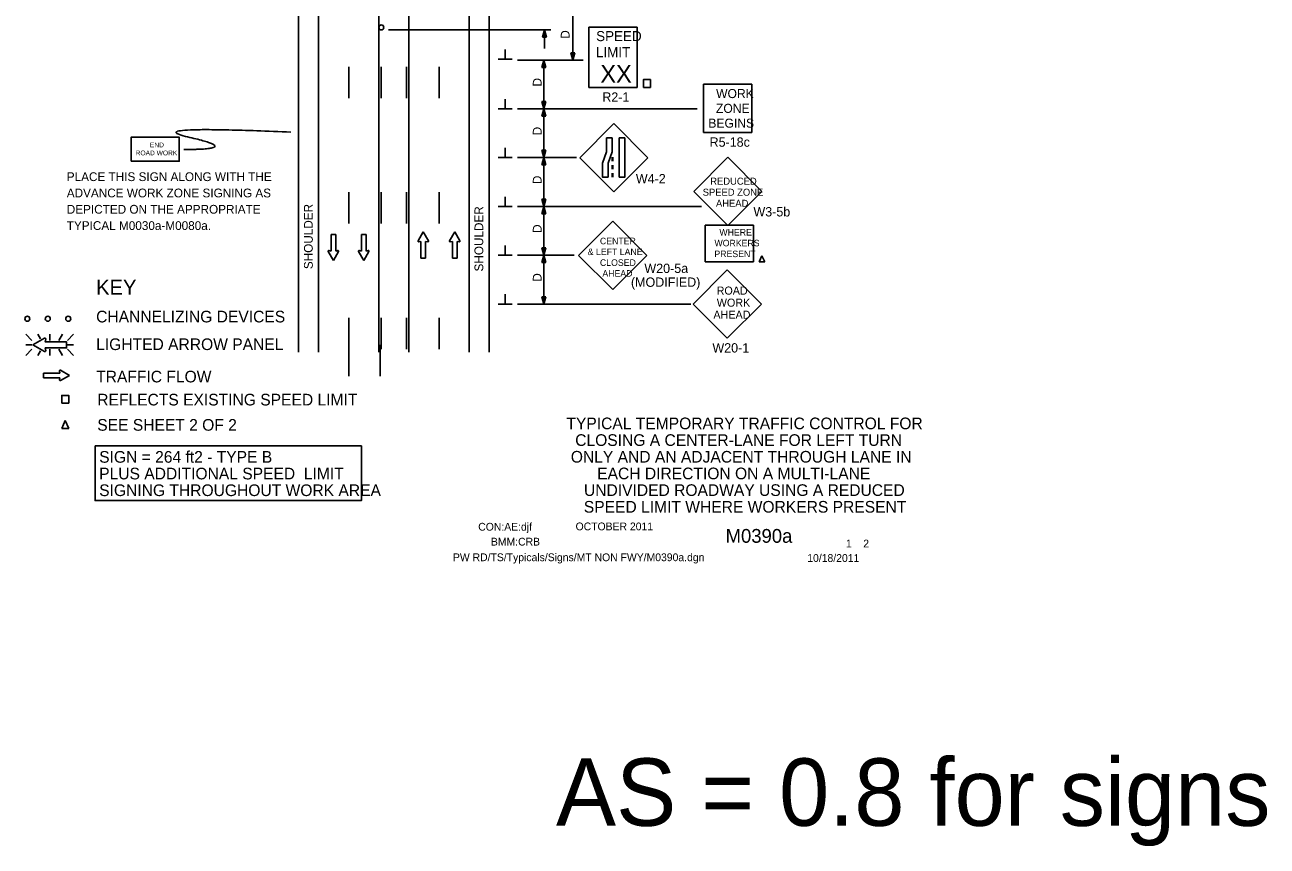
# Model space of a CAD drawing. Extents: x 16729 to 18475, y 5706 to 6927.
# Drawn here: x 16729 to 17719, y 5706 to 6361 of the extents above; entities that cross this region are included whole.
import ezdxf

# ---------------------------------------------------------------- set-up
doc = ezdxf.new("R2010")
doc.units = 0
for name, color, linetype in [('ALI_LEGAL_EX', 7, 'Continuous'), ('BORDER_SIGNAL_WO', 7, 'Continuous'), ('MT_SCRATCH_LEVEL_E', 7, 'Continuous'), ('PAVT_EDGE_EX', 7, 'Continuous'), ('TRAFFIC_SIGNS_PR', 7, 'Continuous'), ('TYPICAL_TEXT_DIMEN_EX', 7, 'Continuous'), ('TYPICAL_TEXT_DIMEN_PR', 7, 'Continuous')]:
    doc.layers.add(name, color=color, linetype=linetype)

msp = doc.modelspace()

# ---------------------------------------------------------------- linework, layer by layer
at = {"layer": 'ALI_LEGAL_EX'}
for points in [[(16987.43, 6327.88), (16987.43, 6302.88)], [(17013.43, 6327.88), (17013.43, 6302.88)], [(17033.43, 6327.88), (17033.43, 6302.88)], [(17059.43, 6327.88), (17059.43, 6302.88)], [(16987.43, 6227.88), (16987.43, 6202.88)], [(17013.43, 6227.88), (17013.43, 6202.88)], [(17033.43, 6227.88), (17033.43, 6202.88)], [(17059.43, 6227.88), (17059.43, 6202.88)], [(16987.43, 6127.88), (16987.43, 6102.88)], [(17013.43, 6127.88), (17013.43, 6102.88)], [(17033.43, 6127.88), (17033.43, 6102.88)], [(17059.43, 6127.88), (17059.43, 6102.88)]]:
    msp.add_lwpolyline(points, dxfattribs=at)
at = {"layer": 'MT_SCRATCH_LEVEL_E'}
for p, q in [((16977.1, 6194.29), (16973.36, 6194.29)), ((16973.36, 6194.29), (16973.36, 6181.03)), ((16977.1, 6194.29), (16973.36, 6194.29)), ((16973.36, 6194.29), (16973.36, 6181.03)), ((16977.1, 6181.03), (16977.1, 6194.29)), ((16977.1, 6181.03), (16977.1, 6194.29)), ((17001.36, 6194.29), (16997.62, 6194.29)), ((16997.62, 6194.29), (16997.62, 6181.03)), ((17001.36, 6194.29), (16997.62, 6194.29)), ((16997.62, 6194.29), (16997.62, 6181.03)), ((17001.36, 6181.03), (17001.36, 6194.29)), ((17001.36, 6181.03), (17001.36, 6194.29)), ((17046.87, 6196.29), (17042.76, 6189.05)), ((17046.87, 6196.29), (17042.76, 6189.05)), ((17043.24, 6188.37), (17045.02, 6188.68)), ((17043.24, 6188.37), (17045.02, 6188.68)), ((17045.02, 6188.68), (17045.02, 6175.42)), ((17045.02, 6188.68), (17045.02, 6175.42)), ((17051.02, 6189.05), (17046.87, 6196.29)), ((17051.02, 6189.05), (17046.87, 6196.29)), ((17048.76, 6175.42), (17048.76, 6188.68)), ((17048.76, 6188.68), (17050.54, 6188.37)), ((17048.76, 6175.42), (17048.76, 6188.68)), ((17048.76, 6188.68), (17050.54, 6188.37)), ((17071.96, 6196.29), (17067.85, 6189.05)), ((17071.96, 6196.29), (17067.85, 6189.05)), ((17068.33, 6188.37), (17070.11, 6188.68)), ((17068.33, 6188.37), (17070.11, 6188.68)), ((17070.11, 6188.68), (17070.11, 6175.42)), ((17070.11, 6188.68), (17070.11, 6175.42)), ((17076.11, 6189.05), (17071.96, 6196.29)), ((17076.11, 6189.05), (17071.96, 6196.29)), ((17073.85, 6175.42), (17073.85, 6188.68)), ((17073.85, 6188.68), (17075.63, 6188.37)), ((17073.85, 6175.42), (17073.85, 6188.68)), ((17073.85, 6188.68), (17075.63, 6188.37)), ((16971.1, 6180.66), (16975.25, 6173.42)), ((16971.1, 6180.66), (16975.25, 6173.42)), ((16973.36, 6181.03), (16971.58, 6181.35)), ((16973.36, 6181.03), (16971.58, 6181.35)), ((16975.25, 6173.42), (16979.36, 6180.66)), ((16975.25, 6173.42), (16979.36, 6180.66)), ((16978.88, 6181.35), (16977.1, 6181.03)), ((16978.88, 6181.35), (16977.1, 6181.03)), ((16995.36, 6180.66), (16999.51, 6173.42)), ((16995.36, 6180.66), (16999.51, 6173.42)), ((16997.62, 6181.03), (16995.84, 6181.35)), ((16997.62, 6181.03), (16995.84, 6181.35)), ((16999.51, 6173.42), (17003.62, 6180.66)), ((16999.51, 6173.42), (17003.62, 6180.66)), ((17003.14, 6181.35), (17001.36, 6181.03)), ((17003.14, 6181.35), (17001.36, 6181.03)), ((17045.02, 6175.42), (17048.76, 6175.42)), ((17045.02, 6175.42), (17048.76, 6175.42)), ((17070.11, 6175.42), (17073.85, 6175.42)), ((17070.11, 6175.42), (17073.85, 6175.42)), ((16757.36, 6083.74), (16744.1, 6083.74)), ((16744.1, 6083.74), (16744.1, 6080)), ((16757.36, 6083.74), (16744.1, 6083.74)), ((16744.1, 6083.74), (16744.1, 6080)), ((16744.1, 6080), (16757.36, 6080)), ((16744.1, 6080), (16757.36, 6080)), ((16757.05, 6085.51), (16757.36, 6083.74)), ((16757.05, 6085.51), (16757.36, 6083.74)), ((16757.36, 6080), (16757.05, 6078.22)), ((16757.36, 6080), (16757.05, 6078.22)), ((16764.97, 6081.89), (16757.73, 6086)), ((16764.97, 6081.89), (16757.73, 6086)), ((16757.73, 6077.74), (16764.97, 6081.89)), ((16757.73, 6077.74), (16764.97, 6081.89))]:
    msp.add_line(p, q, dxfattribs=at)
for centre, start, end in [((17043.17, 6188.83), 150.42484, 279.96381), ((17043.17, 6188.83), 150.42484, 279.96381), ((17050.61, 6188.83), 260.03619, 29.77312), ((17050.61, 6188.83), 260.03619, 29.77312), ((17068.26, 6188.83), 150.42484, 279.96381), ((17068.26, 6188.83), 150.42484, 279.96381), ((17075.7, 6188.83), 260.03619, 29.77312), ((17075.7, 6188.83), 260.03619, 29.77312), ((16971.51, 6180.89), 80.03619, 209.77312), ((16971.51, 6180.89), 80.03619, 209.77312), ((16978.96, 6180.89), 330.42484, 99.96381), ((16978.96, 6180.89), 330.42484, 99.96381), ((16995.77, 6180.89), 80.03619, 209.77312), ((16995.77, 6180.89), 80.03619, 209.77312), ((17003.21, 6180.89), 330.42484, 99.96381), ((17003.21, 6180.89), 330.42484, 99.96381), ((16757.5, 6085.59), 60.42484, 189.96381), ((16757.5, 6085.59), 60.42484, 189.96381), ((16757.51, 6078.15), 170.03619, 299.77312), ((16757.51, 6078.15), 170.03619, 299.77312)]:
    msp.add_arc(centre, 0.463, start, end, dxfattribs=at)
at = {"layer": 'PAVT_EDGE_EX'}
for p, q in [((16947.43, 6859.63), (16947.43, 6100.51)), ((16963.43, 6859.63), (16963.43, 6100.51)), ((17011.43, 6859.63), (17011.43, 6100.51)), ((17035.43, 6859.63), (17035.43, 6100.51)), ((17083.43, 6859.63), (17083.43, 6100.51)), ((17099.43, 6859.63), (17099.43, 6100.51))]:
    msp.add_line(p, q, dxfattribs=at)
for points in [[(16987.43, 6081.34), (16987.43, 6106.34)], [(17012.43, 6081.34), (17012.43, 6106.34)]]:
    msp.add_lwpolyline(points, dxfattribs=at)
at = {"layer": 'TRAFFIC_SIGNS_PR'}
for p, q in [((17178.92, 6359.55), (17217.32, 6359.55)), ((17178.92, 6311.55), (17178.92, 6359.55)), ((17217.32, 6311.55), (17217.32, 6359.55)), ((17178.92, 6311.55), (17217.32, 6311.55)), ((17270.29, 6275.63), (17270.29, 6314.03)), ((17270.29, 6314.03), (17308.69, 6314.03)), ((17308.69, 6275.63), (17308.69, 6314.03)), ((17198.74, 6282.6), (17171.58, 6255.44)), ((17225.89, 6255.44), (17198.74, 6282.6)), ((17270.29, 6275.63), (17308.69, 6275.63)), ((17171.58, 6255.44), (17198.74, 6228.29)), ((17197.49, 6255.93), (17197.49, 6252.73)), ((17197.49, 6249.53), (17197.49, 6246.33)), ((17197.89, 6255.93), (17197.89, 6252.73)), ((17197.89, 6249.53), (17197.89, 6246.33)), ((17198.74, 6228.29), (17225.89, 6255.44)), ((17289.56, 6255.77), (17262.41, 6228.61)), ((17316.71, 6228.61), (17289.56, 6255.77)), ((17197.49, 6243.13), (17197.49, 6239.93)), ((17197.89, 6243.13), (17197.89, 6239.93)), ((17262.41, 6228.61), (17289.56, 6201.46)), ((17289.56, 6201.46), (17316.71, 6228.61)), ((17197.92, 6204.73), (17170.74, 6177.55)), ((17225.11, 6177.55), (17197.92, 6204.73)), ((17271.6, 6201.69), (17310, 6201.69)), ((17271.6, 6172.37), (17271.6, 6201.69)), ((17310, 6172.37), (17310, 6201.69)), ((17170.74, 6177.55), (17197.92, 6150.36)), ((17197.92, 6150.36), (17225.11, 6177.55)), ((17271.6, 6172.37), (17310, 6172.37)), ((17289.18, 6165.92), (17261.99, 6138.73)), ((17316.37, 6138.73), (17289.18, 6165.92)), ((17261.99, 6138.73), (17289.18, 6111.54)), ((17289.18, 6111.54), (17316.37, 6138.73)), ((16730.08, 6114.7), (16735.02, 6109.77)), ((16741.84, 6110.88), (16739.64, 6114.7)), ((16749.16, 6109.77), (16749.16, 6114.7)), ((16756.4, 6109.77), (16759.25, 6114.7)), ((16763.31, 6109.77), (16768.25, 6114.71)), ((16735.02, 6106.21), (16730.08, 6106.21)), ((16730.08, 6097.72), (16735.02, 6102.66)), ((16739.59, 6097.72), (16741.71, 6101.38)), ((16749.16, 6102.66), (16749.16, 6097.72)), ((16759.29, 6097.72), (16756.44, 6102.66)), ((16763.31, 6106.21), (16768.25, 6106.21)), ((16763.31, 6102.66), (16768.25, 6097.72))]:
    msp.add_line(p, q, dxfattribs=at)
for points in [[(17222.33, 6311.55), (17227.93, 6311.55), (17227.93, 6317.72), (17222.33, 6317.72)], [(16814.04, 6252.59), (16852.44, 6252.59), (16852.44, 6271.79), (16814.04, 6271.79)], [(17197.49, 6271.18), (17197.49, 6260), (17194.14, 6251.12), (17194.14, 6239.93), (17189.65, 6239.93), (17189.65, 6251.12), (17192.99, 6260), (17192.99, 6271.18)], [(17207.62, 6271.18), (17207.62, 6239.93), (17203.13, 6239.93), (17203.13, 6271.18)], [(16758.75, 6059.72), (16764.35, 6059.72), (16764.35, 6065.89), (16758.75, 6065.89)]]:
    msp.add_lwpolyline(points, close=True, dxfattribs=at)
for points in [[(17316.75, 6177.31), (17314.52, 6172.37)], [(17314.52, 6172.37), (17316.75, 6177.31)], [(17314.52, 6172.37), (17318.99, 6172.37)], [(17318.99, 6172.37), (17314.52, 6172.37)], [(17318.99, 6172.37), (17316.75, 6177.31)], [(17316.75, 6177.31), (17318.99, 6172.37)], [(16745.09, 6111.49), (16735.8, 6106.21), (16745.09, 6100.89)], [(16745.97, 6101.52), (16745.57, 6103.79), (16762.58, 6103.79), (16762.58, 6108.59), (16745.57, 6108.59), (16745.97, 6110.87)], [(16761.55, 6045.76), (16758.75, 6039.59)], [(16758.75, 6039.59), (16761.55, 6045.76)], [(16764.35, 6039.59), (16761.55, 6045.76)], [(16761.55, 6045.76), (16764.35, 6039.59)], [(16758.75, 6039.59), (16764.35, 6039.59)], [(16764.35, 6039.59), (16758.75, 6039.59)]]:
    msp.add_lwpolyline(points, dxfattribs=at)
for centre in [(17013.45, 6359.33), (17013.45, 6359.33), (16731.34, 6127.04), (16747.64, 6127.04), (16763.94, 6127.04)]:
    msp.add_circle(centre, 2, dxfattribs=at)
for centre, radius, start, end in [((16745.38, 6110.97), 0.598, 350.73078, 118.89165), ((16745.38, 6101.42), 0.597, 241.48329, 9.95933)]:
    msp.add_arc(centre, radius, start, end, dxfattribs=at)
msp.add_open_spline([(16856.03, 6261.97), (16903.27, 6261.97), (16818.24, 6281.32), (16941.34, 6275.83)], degree=2, dxfattribs=at)
at = {"layer": 'TYPICAL_TEXT_DIMEN_EX'}
msp.add_lwpolyline([(16785.26, 6025.6), (16997.53, 6025.6), (16997.53, 5981.98), (16785.26, 5981.98)], close=True, dxfattribs=at)
at = {"layer": 'TYPICAL_TEXT_DIMEN_PR'}
for p, q in [((17166.05, 6372.25), (17166.05, 6333.33)), ((17148.43, 6357.33), (17019.11, 6357.33)), ((17143.43, 6357.33), (17141.86, 6351.47)), ((17143.43, 6357.33), (17143.43, 6342.41)), ((17145, 6351.47), (17143.43, 6357.33)), ((17141.86, 6351.47), (17143.43, 6351.47)), ((17143.43, 6351.47), (17145, 6351.47)), ((17112.19, 6333.98), (17112.19, 6341.77)), ((17166.05, 6333.33), (17164.48, 6339.19)), ((17164.48, 6339.19), (17166.05, 6339.19)), ((17166.05, 6339.19), (17167.62, 6339.19)), ((17167.62, 6339.19), (17166.05, 6333.33)), ((17117.82, 6333.98), (17106.57, 6333.98)), ((17174.43, 6333.33), (17122.07, 6333.33)), ((17141.5, 6327.47), (17143.07, 6333.33)), ((17143.07, 6327.47), (17141.5, 6327.47)), ((17143.07, 6333.33), (17143.07, 6294.41)), ((17143.07, 6333.33), (17144.64, 6327.47)), ((17144.64, 6327.47), (17143.07, 6327.47)), ((17112.19, 6294.41), (17112.19, 6302.19)), ((17143.07, 6294.41), (17141.5, 6300.27)), ((17141.5, 6300.27), (17143.07, 6300.27)), ((17143.07, 6300.27), (17144.64, 6300.27)), ((17144.64, 6300.27), (17143.07, 6294.41)), ((17117.82, 6294.41), (17106.57, 6294.41)), ((17265.06, 6294.41), (17122.07, 6294.41)), ((17141.5, 6288.55), (17143.07, 6294.41)), ((17143.07, 6288.55), (17141.5, 6288.55)), ((17143.07, 6294.41), (17143.07, 6255.49)), ((17143.07, 6294.41), (17144.64, 6288.55)), ((17144.64, 6288.55), (17143.07, 6288.55)), ((17112.19, 6255.49), (17112.19, 6263.28)), ((17143.07, 6255.49), (17141.5, 6261.35)), ((17141.5, 6261.35), (17143.07, 6261.35)), ((17143.07, 6261.35), (17144.64, 6261.35)), ((17144.64, 6261.35), (17143.07, 6255.49)), ((17117.82, 6255.49), (17106.57, 6255.49)), ((17168.96, 6255.49), (17122.07, 6255.49)), ((17141.5, 6249.63), (17143.07, 6255.49)), ((17143.07, 6249.63), (17141.5, 6249.63)), ((17143.07, 6255.49), (17143.07, 6216.57)), ((17143.07, 6255.49), (17144.64, 6249.63)), ((17144.64, 6249.63), (17143.07, 6249.63)), ((17112.19, 6216.57), (17112.19, 6224.36)), ((17143.07, 6216.57), (17141.5, 6222.43)), ((17141.5, 6222.43), (17143.07, 6222.43)), ((17143.07, 6222.43), (17144.64, 6222.43)), ((17144.64, 6222.43), (17143.07, 6216.57)), ((17117.82, 6216.57), (17106.57, 6216.57)), ((17268.52, 6216.57), (17122.07, 6216.57)), ((17141.5, 6210.71), (17143.07, 6216.57)), ((17143.07, 6210.71), (17141.5, 6210.71)), ((17143.07, 6216.57), (17143.07, 6177.65)), ((17143.07, 6216.57), (17144.64, 6210.71)), ((17144.64, 6210.71), (17143.07, 6210.71)), ((17112.19, 6177.65), (17112.19, 6185.44)), ((17143.07, 6177.65), (17141.5, 6183.51)), ((17141.5, 6183.51), (17143.07, 6183.51)), ((17143.07, 6183.51), (17144.64, 6183.51)), ((17144.64, 6183.51), (17143.07, 6177.65)), ((17117.82, 6177.65), (17106.57, 6177.65)), ((17167.23, 6177.65), (17122.07, 6177.65)), ((17141.5, 6171.79), (17143.07, 6177.65)), ((17143.07, 6171.79), (17141.5, 6171.79)), ((17143.07, 6177.65), (17143.07, 6138.73)), ((17143.07, 6177.65), (17144.64, 6171.79)), ((17144.64, 6171.79), (17143.07, 6171.79)), ((17112.19, 6138.73), (17112.19, 6146.52)), ((17143.07, 6138.73), (17141.5, 6144.59)), ((17141.5, 6144.59), (17143.07, 6144.59)), ((17143.07, 6144.59), (17144.64, 6144.59)), ((17144.64, 6144.59), (17143.07, 6138.73)), ((17117.82, 6138.73), (17106.57, 6138.73)), ((17260.16, 6138.73), (17122.07, 6138.73))]:
    msp.add_line(p, q, dxfattribs=at)

# ---------------------------------------------------------------- texts
at = {"layer": 'BORDER_SIGNAL_WO'}
for s, height, p in [('TYPICAL TEMPORARY TRAFFIC CONTROL FOR', 9.3, (17160.98, 6038.92)), ('CLOSING A CENTER-LANE FOR LEFT TURN', 9.3, (17167.98, 6025.62)), ('ONLY AND AN ADJACENT THROUGH LANE IN', 9.3, (17164.48, 6012.32)), ('EACH DIRECTION ON A MULTI-LANE', 9.3, (17185.5, 5999.02)), ('UNDIVIDED ROADWAY USING A REDUCED', 9.3, (17174.96, 5985.72)), ('SPEED LIMIT WHERE WORKERS PRESENT', 9.3, (17174.85, 5972.42)), ('CON:AE:djf', 6.2, (17090.69, 5958.06)), ('    OCTOBER 2011    ', 6.2, (17159.08, 5958.34)), ('BMM:CRB   ', 6.2, (17100.81, 5946.17)), ('    M0390a   ', 11, (17271.53, 5948.38)), (' 1    2 ', 6.2, (17381.45, 5944.7)), ('PW RD/TS/Typicals/Signs/MT NON FWY/M0390a.dgn    ', 6.2, (17070.55, 5933.71)), ('10/18/2011    ', 6.2, (17352.93, 5933.13))]:
    msp.add_text(s, height=height, dxfattribs=at).set_placement(p)
at = {"layer": 'TRAFFIC_SIGNS_PR'}
for s, height, p in [('SPEED', 8, (17184.68, 6348.41)), ('LIMIT', 8, (17184.52, 6335.61)), ('XX', 14.031, (17188.03, 6315.31)), ('R2-1', 7.44, (17189.59, 6300.11)), ('WORK', 7.217, (17280.29, 6303)), ('ZONE', 7.217, (17280.17, 6291.19)), ('BEGINS', 7.217, (17274.1, 6279.38)), ('END', 3.831, (16829.04, 6263.72)), ('R5-18c', 7.44, (17275.1, 6264.19)), ('ROAD WORK', 3.831, (16817.65, 6257.33)), ('PLACE THIS SIGN ALONG WITH THE', 7, (16762.76, 6236.81)), ('W4-2', 7.44, (17216.33, 6235.02)), ('REDUCED', 5.6, (17275.62, 6233.92)), ('ADVANCE WORK ZONE SIGNING AS', 7, (16762.76, 6223.81)), ('SPEED ZONE', 5.6, (17269.61, 6225.12)), ('AHEAD', 5.6, (17280.17, 6216.32)), ('DEPICTED ON THE APPROPRIATE', 7, (16762.76, 6210.81)), ('W3-5b', 7.44, (17310.05, 6208.61)), ('TYPICAL M0030a-M0080a.', 7, (16762.76, 6197.81)), ('WHERE', 5.2, (17282.91, 6193.37)), ('CENTER', 5.206, (17187.69, 6186.4)), ('WORKERS', 5.2, (17278.99, 6184.77)), ('& LEFT LANE', 5.2065, (17177.95, 6177.79)), ('PRESENT', 5.2, (17278.92, 6176.17)), ('CLOSED', 5.206, (17187.69, 6169.18)), ('W20-5a', 7.449, (17223.12, 6163.5)), ('AHEAD', 5.206, (17189.64, 6160.57)), ('(MODIFIED)', 7.449, (17212.4, 6152.49)), ('ROAD', 6.408, (17280.71, 6146.27)), ('WORK', 6.408, (17280.82, 6136.66)), ('AHEAD', 6.408, (17278.13, 6127.05)), ('W20-1', 7.449, (17277.33, 6100.09))]:
    msp.add_text(s, height=height, dxfattribs=at).set_placement(p)
at = {"layer": 'TYPICAL_TEXT_DIMEN_EX'}
for s, height, p in [('KEY', 12, (16786.18, 6146.15)), ('CHANNELIZING DEVICES', 9.3, (16786.18, 6124.1)), ('LIGHTED ARROW PANEL', 9.3, (16786.18, 6102.05)), ('TRAFFIC FLOW', 9.3, (16786.18, 6076.25)), ('REFLECTS EXISTING SPEED LIMIT', 9.3, (16787.06, 6057.88)), ('SEE SHEET 2 OF 2', 9.3, (16787.06, 6037.75)), ('SIGN = 264 ft2 - TYPE B', 9.3, (16788.6, 6012.23)), ('PLUS ADDITIONAL SPEED  LIMIT', 9.3, (16788.6, 5998.93)), ('SIGNING THROUGHOUT WORK AREA', 9.3, (16788.6, 5985.63))]:
    msp.add_text(s, height=height, dxfattribs=at).set_placement(p)
at = {"layer": 'TYPICAL_TEXT_DIMEN_PR'}
for s, p in [('D', (17163.49, 6350.31)), ('D', (17141.2, 6312.25)), ('D', (17141.2, 6273.33)), ('D', (17141.2, 6234.41)), ('SHOULDER', (16958.81, 6166.58)), ('SHOULDER', (17094.71, 6164.73)), ('D', (17141.2, 6195.49)), ('D', (17141.2, 6156.57))]:
    msp.add_text(s, height=7, rotation=90, dxfattribs=at).set_placement(p)
msp.add_text('AS = 0.8 for signs', height=53.76, dxfattribs=at).set_placement((17152.63, 5722.68))

doc.saveas('drawing.dxf')
